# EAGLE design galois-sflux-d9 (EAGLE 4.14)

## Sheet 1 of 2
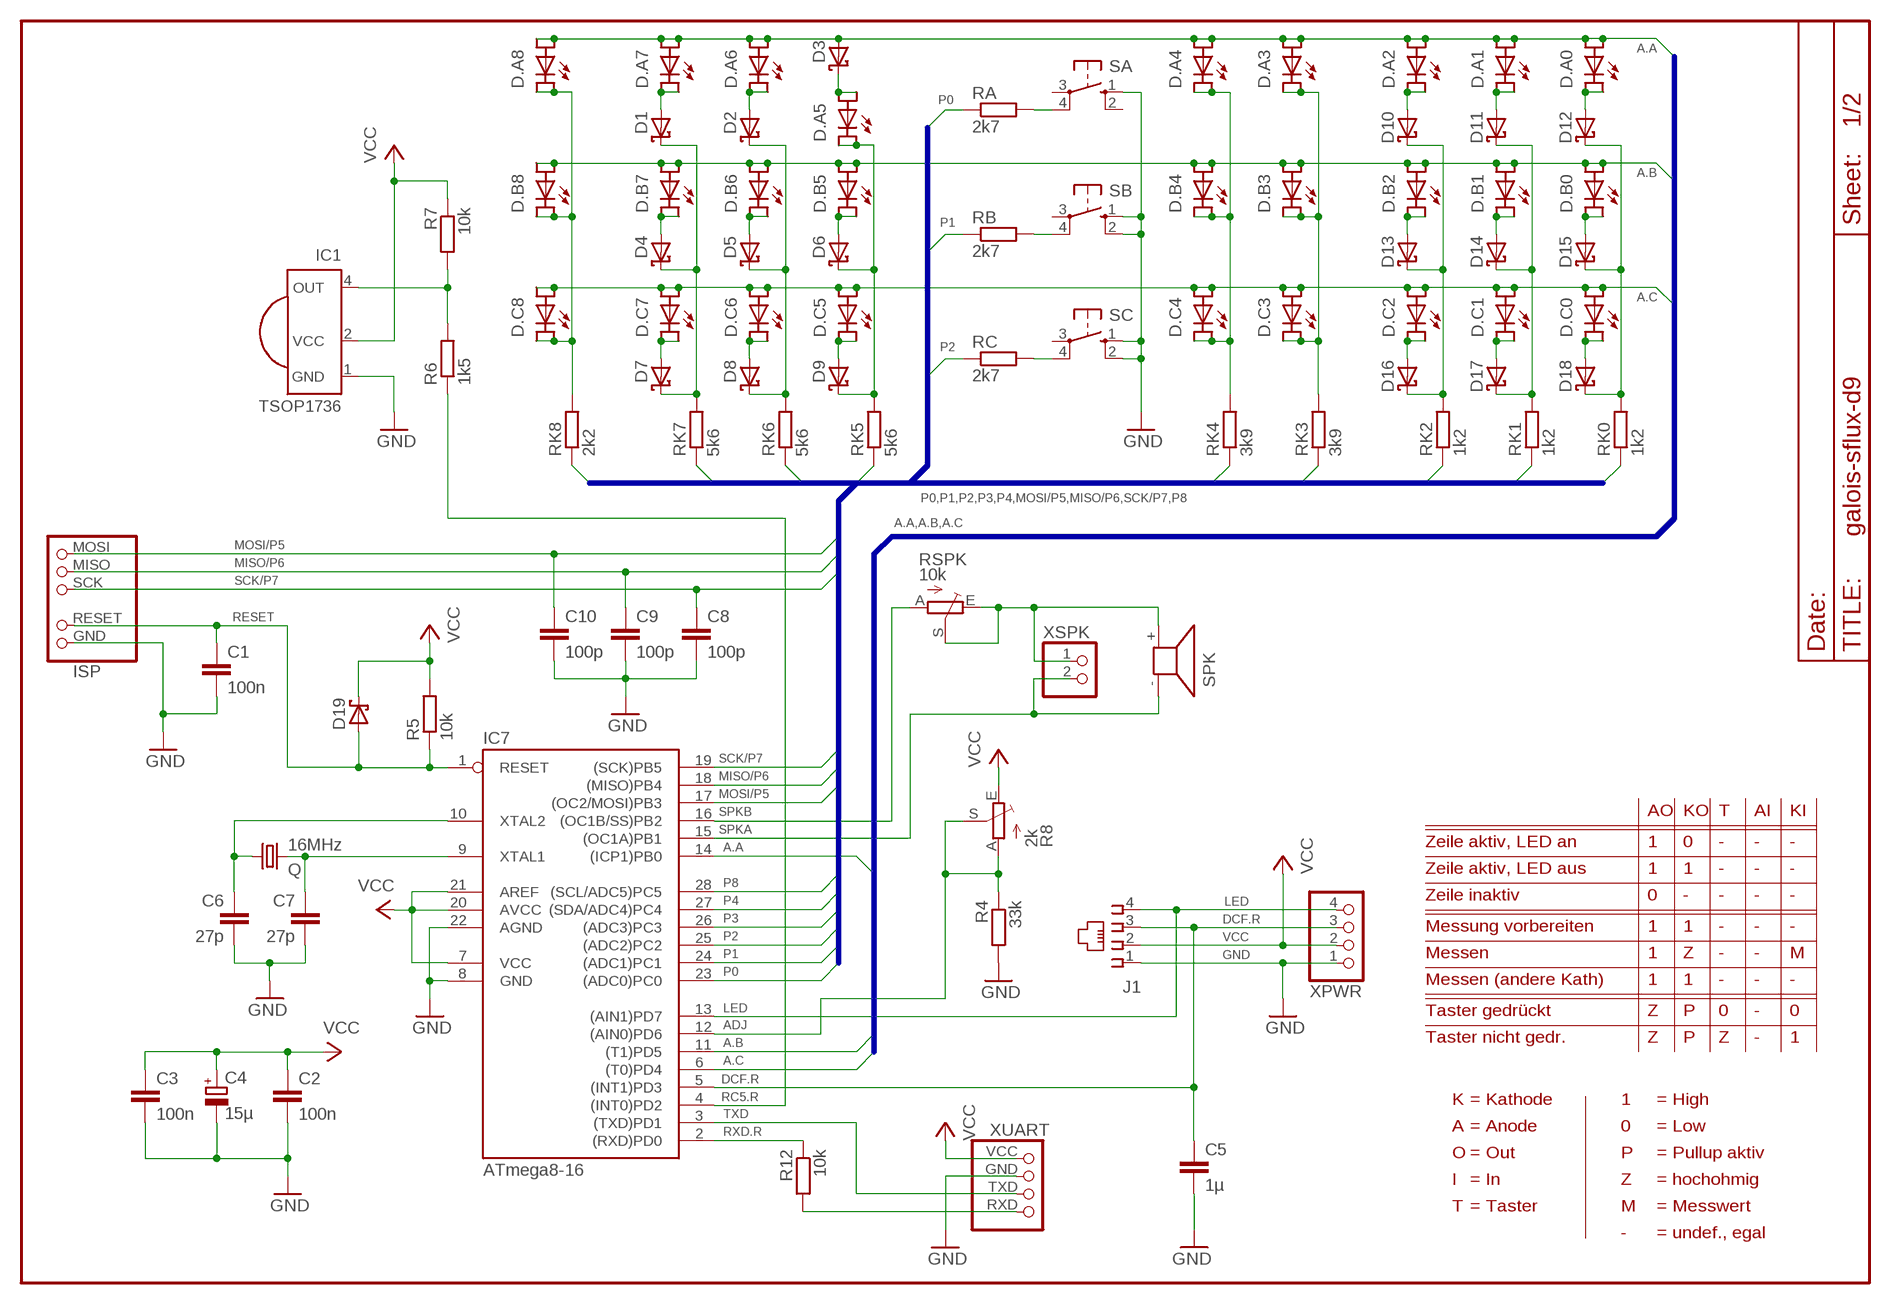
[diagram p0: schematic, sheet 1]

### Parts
C1  100n  C-EU050-024X044  [C050-024X044]
C2  100n  C-EU050-024X044  [C050-024X044]
C3  100n  C-EU050-024X044  [C050-024X044]
C4  15µ  CPOL-EUE1.8-4  [E1,8-4]
C5  1µ  C-EU050-024X044  [C050-024X044]
C6  27p  C-EU025-025X050  [C025-025X050]
C7  27p  C-EU025-025X050  [C025-025X050]
C8  100p  C-EU025-025X050  [C025-025X050]
C9  100p  C-EU025-025X050  [C025-025X050]
C10  100p  C-EU025-025X050  [C025-025X050]
D1  BAT42  [DO35-10@1]
D2  BAT42-7  [DO35-7B]
D3  BAT42-2.5  [DO35-2.5]
D4  BAT42  [DO35-10]
D5  BAT42-5  [DO35-5]
D6  BAT42-5  [DO35-5]
D7  BAT42-2.5  [DO35-2.5]
D8  BAT42-2.5  [DO35-2.5]
D9  BAT42-2.5  [DO35-2.5]
D10  BAT42  [DO35-10]
D11  BAT42  [DO35-10]
D12  BAT42  [DO35-10]
D13  BAT42  [DO35-10]
D14  BAT42  [DO35-10]
D15  BAT42  [DO35-10]
D16  BAT42  [DO35-10@1]
D17  BAT42-5  [DO35-5]
D18  BAT42  [DO35-10@1]
D19  BAT42  [DO35-10@1]
D.A0  LEDFLUX  [SFLUX]
D.A1  LEDFLUX  [SFLUX]
D.A2  LEDFLUX  [SFLUX]
D.A3  LEDFLUX  [SFLUX]
D.A4  LEDFLUX  [SFLUX]
D.A5  LEDFLUX  [SFLUX]
D.A6  LEDFLUX  [SFLUX]
D.A7  LEDFLUX  [SFLUX]
D.A8  LEDFLUX  [SFLUX]
D.B0  LEDFLUX  [SFLUX]
D.B1  LEDFLUX  [SFLUX]
D.B2  LEDFLUX  [SFLUX]
D.B3  LEDFLUX  [SFLUX]
D.B4  LEDFLUX  [SFLUX]
D.B5  LEDFLUX  [SFLUX]
D.B6  LEDFLUX  [SFLUX]
D.B7  LEDFLUX  [SFLUX]
D.B8  LEDFLUX  [SFLUX]
D.C0  LEDFLUX  [SFLUX]
D.C1  LEDFLUX  [SFLUX]
D.C2  LEDFLUX  [SFLUX]
D.C3  LEDFLUX  [SFLUX]
D.C4  LEDFLUX  [SFLUX]
D.C5  LEDFLUX  [SFLUX]
D.C6  LEDFLUX  [SFLUX]
D.C7  LEDFLUX  [SFLUX]
D.C8  LEDFLUX  [SFLUX]
IC1  TSOP1736  TSOPH  [TSOP-H]
IC7  ATmega8-16  MEGA8  [DIL28-3]
ISP  ISP  [PINHD6.ISP]
J1  MODULAR4  [MODULAR4-1]
Q  16MHz  CRYTALHC18U-V  [HC18U-V]
R4  33k  R-EU_0204/5  [0204/5]
R5  10k  R-EU_0204/5  [0204/5]
R6  1k5  R-EU_0204/5  [0204/5]
R7  10k  R-EU_0204/7  [0204/7]
R8  2k  TRIM_EU-S75H  [S75H]
R12  10k  R-EU_0204/5  [0204/5]
RA  2k7  R-EU_0204/7  [0204/7]
RB  2k7  R-EU_0204/5  [0204/5]
RC  2k7  R-EU_0204/5  [0204/5]
RK0  1k2  R-EU_0204/5  [0204/5]
RK1  1k2  R-EU_0204/5  [0204/5]
RK2  1k2  R-EU_0204/5  [0204/5]
RK3  3k9  R-EU_0204/5  [0204/5]
RK4  3k9  R-EU_0204/5  [0204/5]
RK5  5k6  R-EU_0204/5  [0204/5]
RK6  5k6  R-EU_0204/5  [0204/5]
RK7  5k6  R-EU_0204/5  [0204/5]
RK8  2k2  R-EU_0204/5  [0204/5]
RSPK  10k  TRIM_EU-S75H  [S75H]
SA  10-XX  [B3F-10XX]
SB  10-XX  [B3F-10XX]
SC  10-XX  [B3F-10XX]
SPK  AL11P  [AL11P]
XPWR  PINHD-1X4  [1X04]
XSPK  PINHD-1X2  [1X02]
XUART  UART  [PINHD4.UART]

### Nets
A.A: D3.A D.A0.A1 D.A0.A2 D.A1.A1 D.A1.A2 D.A2.A1 D.A2.A2 D.A3.A1 D.A3.A2 D.A4.A1 D.A4.A2 D.A6.A1 D.A6.A2 D.A7.A1 D.A7.A2 D.A8.A1 D.A8.A2 IC7.14((ICP1)PB0)
A.B: D.B0.A1 D.B0.A2 D.B1.A1 D.B1.A2 D.B2.A1 D.B2.A2 D.B3.A1 D.B3.A2 D.B4.A1 D.B4.A2 D.B5.A1 D.B5.A2 D.B6.A1 D.B6.A2 D.B7.A1 D.B7.A2 D.B8.A1 D.B8.A2 IC7.11((T1)PD5)
A.C: D.C0.A1 D.C0.A2 D.C1.A1 D.C1.A2 D.C2.A1 D.C2.A2 D.C3.A1 D.C3.A2 D.C4.A1 D.C4.A2 D.C5.A1 D.C5.A2 D.C6.A1 D.C6.A2 D.C7.A1 D.C7.A2 D.C8.A1 D.C8.A2 IC7.6((T0)PD4)
ADJ: IC7.12((AIN0)PD6) R4.1 R8.A R8.S
D.A3: D.A3.K1 D.A3.K2 D.B3.K1 D.B3.K2 D.C3.K1 D.C3.K2 RK3.2
DCF.R: C5.1 IC7.5((INT1)PD3) J1.3 XPWR.3 ; also sheet 2
GND: C1.2 C2.2 C3.2 C4.- C5.2 C6.2 C7.2 C8.2 C9.2 C10.2 IC1.1(GND) IC7.8(GND) IC7.22(AGND) ISP.GND J1.1 R4.2 SA.1(S) SB.1(S) SB.2(S1) SC.1(S) SC.2(S1) XPWR.1 XUART.GND ; also sheet 2
K0: D12.C D15.C D18.C RK0.2
K1: D11.C D14.C D17.C RK1.2
K2: D10.C D13.C D16.C RK2.2
K4: D.A4.K1 D.A4.K2 D.B4.K1 D.B4.K2 D.C4.K1 D.C4.K2 RK4.2
K5: D6.C D9.C D.A5.K1 D.A5.K2 RK5.2
K6: D2.C D5.C D8.C RK6.2
K7: D1.C D4.C D7.C RK7.2
K8: D.A8.K1 D.A8.K2 D.B8.K1 D.B8.K2 D.C8.K1 D.C8.K2 RK8.2
LED: IC7.13((AIN1)PD7) J1.4 XPWR.4 ; also sheet 2
MISO/P6: C9.1 IC7.18((MISO)PB4) ISP.MISO RK6.1
MOSI/P5: C10.1 IC7.17((OC2/MOSI)PB3) ISP.MOSI RK5.1
N$1: D7.A D.C7.K1 D.C7.K2
N$2: D8.A D.C6.K1 D.C6.K2
N$3: D9.A D.C5.K1 D.C5.K2
N$4: D18.A D.C0.K1 D.C0.K2
N$5: D13.A D.B2.K1 D.B2.K2
N$6: D14.A D.B1.K1 D.B1.K2
N$7: D17.A D.C1.K1 D.C1.K2
N$8: D16.A D.C2.K1 D.C2.K2
N$9: D15.A D.B0.K1 D.B0.K2
N$10: D12.A D.A0.K1 D.A0.K2
N$11: D11.A D.A1.K1 D.A1.K2
N$12: D10.A D.A2.K1 D.A2.K2
N$13: D1.A D.A7.K1 D.A7.K2
N$14: D4.A D.B7.K1 D.B7.K2
N$15: D5.A D.B6.K1 D.B6.K2
N$16: D2.A D.A6.K1 D.A6.K2
N$17: D3.C D.A5.A1 D.A5.A2
N$18: D6.A D.B5.K1 D.B5.K2
P0: IC7.23((ADC0)PC0) RA.1 RK0.1
P1: IC7.24((ADC1)PC1) RB.1 RK1.1
P2: IC7.25((ADC2)PC2) RC.1 RK2.1
P3: IC7.26((ADC3)PC3) RK3.1
P4: IC7.27((SDA/ADC4)PC4) RK4.1
P8: IC7.28((SCL/ADC5)PC5) RK8.1
RC5: IC1.4(OUT) R6.2 R7.2
RC5.R: IC7.4((INT0)PD2) R6.1
RESET: C1.1 D19.A IC7.1(RESET) ISP.RESET R5.1
RXD: R12.2 XUART.RXD
RXD.R: IC7.2((RXD)PD0) R12.1
SA.R: RA.2 SA.4(P1)
SB.R: RB.2 SB.4(P1)
SC.R: RC.2 SC.4(P1)
SCK/P7: C8.1 IC7.19((SCK)PB5) ISP.SCK RK7.1
SPK.R: RSPK.E RSPK.S SPK.+ XSPK.1
SPKA: IC7.15((OC1A)PB1) SPK.- XSPK.2
SPKB: IC7.16((OC1B/SS)PB2) RSPK.A
TXD: IC7.3((TXD)PD1) XUART.TXD
VCC: C2.1 C3.1 C4.+ D19.C IC1.2(VCC) IC7.7(VCC) IC7.20(AVCC) IC7.21(AREF) J1.2 R5.2 R7.1 R8.E XPWR.2 XUART.VCC ; also sheet 2
XTAL1: C6.1 IC7.10(XTAL2) Q.1
XTAL2: C7.1 IC7.9(XTAL1) Q.2
Unconnected: SA.2(S1) SA.3(P) SB.3(P) SC.3(P)

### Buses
P0,P1,P2,P3,P4,MOSI/P5,MISO/P6,SCK/P7,P8
A.A,A.B,A.C

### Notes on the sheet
- AO | KO | T | AI | KI
- Zeile aktiv, LED an | 1 | 0 | - | - | -
- Zeile aktiv, LED aus | 1 | 1 | - | - | -
- Zeile inaktiv | 0 | - | - | - | -
- Messung vorbereiten | 1 | 1 | - | - | -
- Messen | 1 | Z | - | - | M
- Messen (andere Kath) | 1 | 1 | - | - | -
- Taster gedrückt | Z | P | 0 | - | 0
- Taster nicht gedr. | Z | P | Z | - | 1
- K | = Kathode | 1 | = High
- A | = Anode | 0 | = Low
- O | = Out | P | = Pullup aktiv
- I | = In | Z | = hochohmig
- T | = Taster | M | = Messwert
- - | = undef., egal

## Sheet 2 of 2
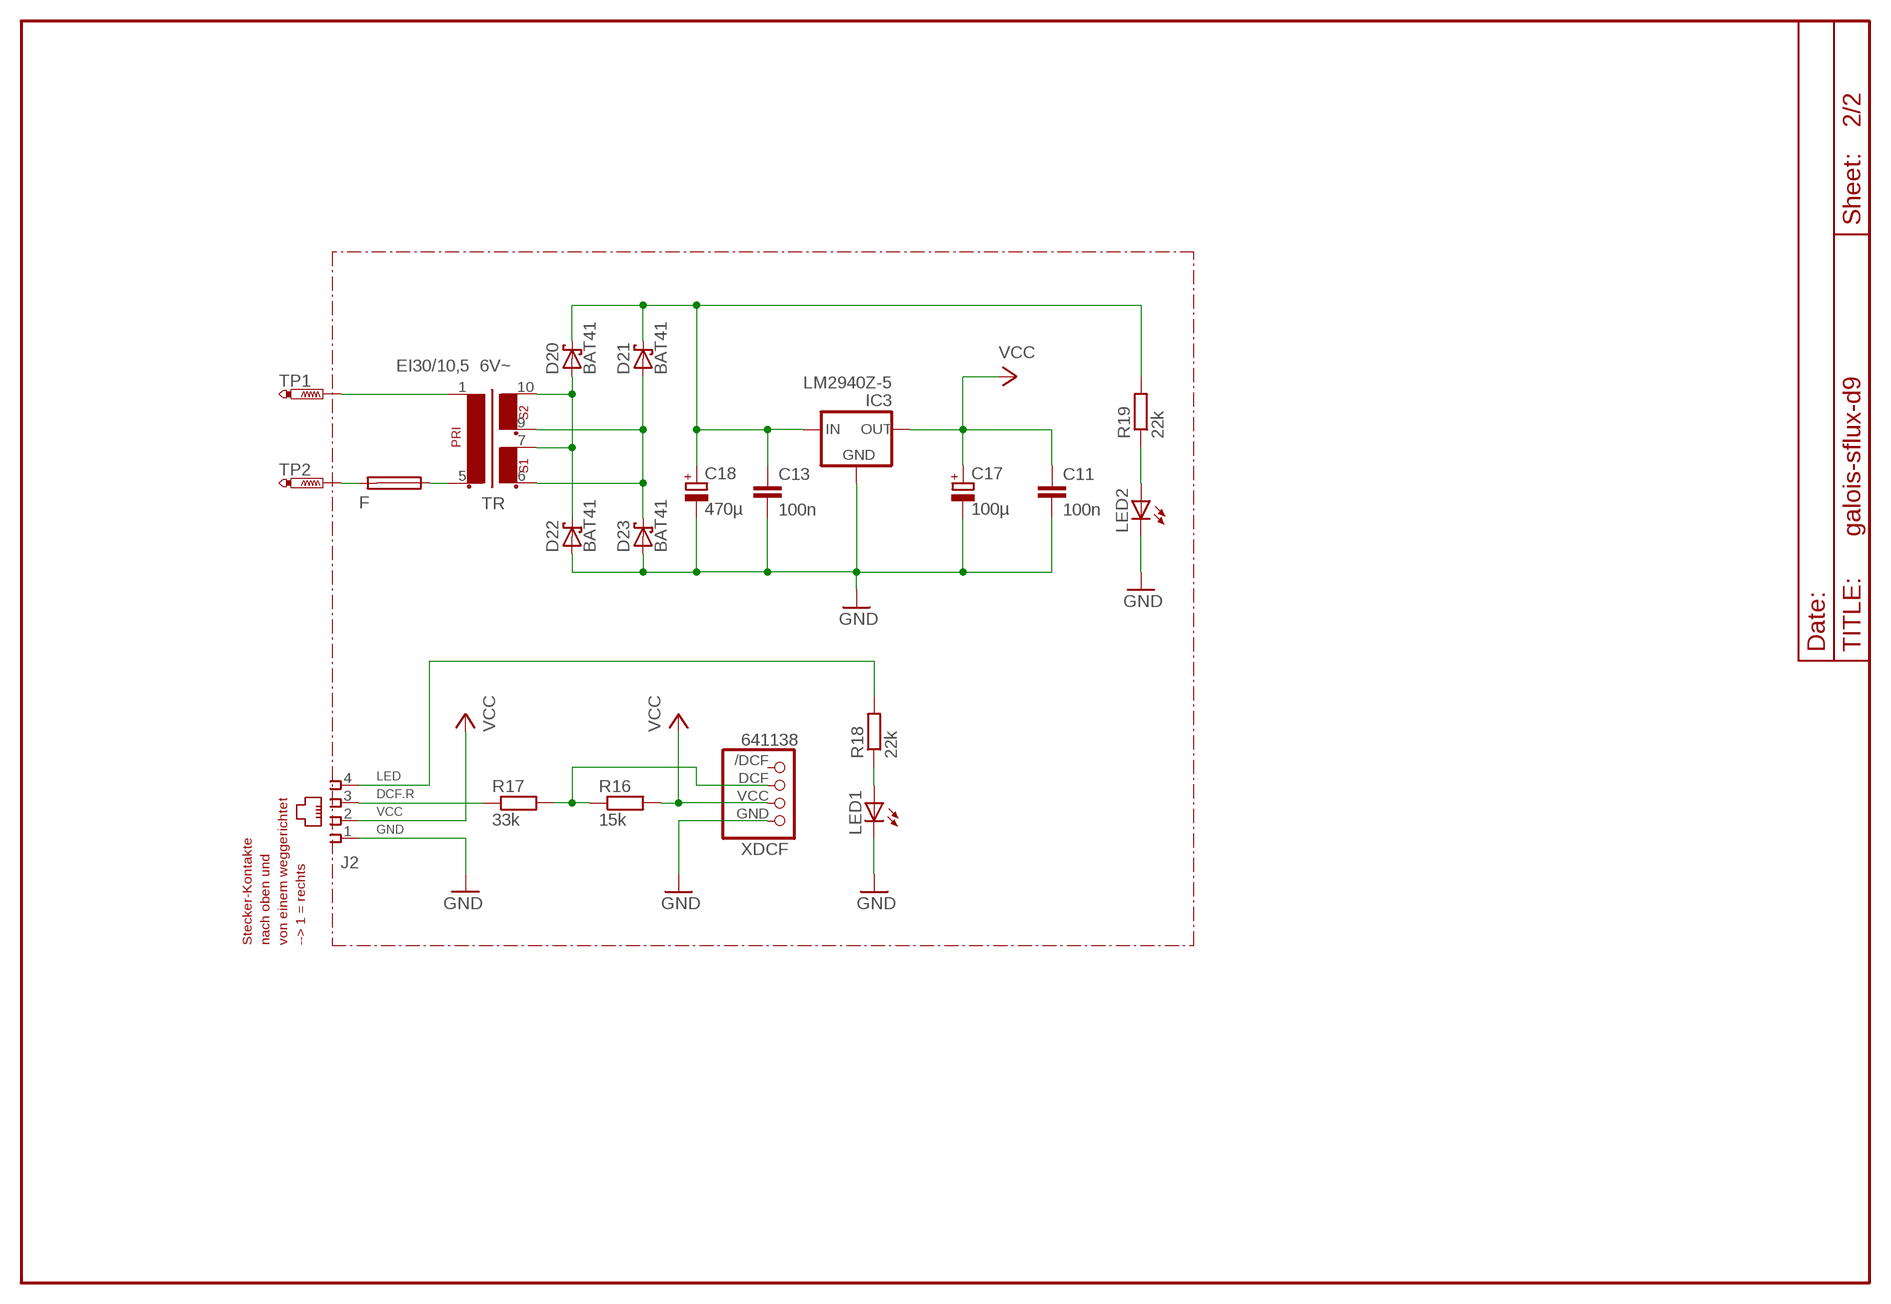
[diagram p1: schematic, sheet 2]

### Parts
C11  100n  C-EU050-024X044  [C050-024X044]
C13  100n  C-EU050-024X044  [C050-024X044]
C17  100µ  CPOL-EUE2.5-6  [E2,5-6]
C18  470µ  CPOL-EUE5-10.5  [E5-10,5]
D20  BAT41  BAT42  [DO35-10]
D21  BAT41  BAT42  [DO35-10]
D22  BAT41  BAT42  [DO35-10]
D23  BAT41  BAT42  [DO35-10]
F  F457  [F457]
IC3  LM2940Z-5  78XXS  [78XXS]
J2  MODULAR4H  [MODULAR4-1H]
LED1  LED3MM  [LED3MM]
LED2  LED3MM  [LED3MM]
R16  15k  R-EU_0207/10  [0207/10]
R17  33k  R-EU_0207/10  [0207/10]
R18  22k  R-EU_0207/10  [0207/10]
R19  22k  R-EU_0204/7  [0204/7]
TP1  PTR1PAD1-20Y  [P1-20Y]
TP2  PTR1PAD1-20Y  [P1-20Y]
TR  EI30/10,5 6V~  EI30-2  [EI30-2]
XDCF  641138  DCFV  [PINHEAD7-4.DCF]

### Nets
6V.A: D21.A D23.C TR.6 TR.9
6V.B: D20.A D22.C TR.7 TR.10
230V.A: TP1.1(TP) TR.1
230V.B: F.1 TR.5
DCF: R16.1 R17.2 XDCF.DCF
DCF.R: J2.3 R17.1 ; also sheet 1
GND: C11.2 C13.2 C17.- C18.- D22.A D23.A IC3.GND J2.1 LED1.K(C) LED2.K(C) XDCF.GND ; also sheet 1
LED: J2.4 R18.2 ; also sheet 1
LED1: LED1.A R18.1
LED2: LED2.A R19.1
N$19: F.2 TP2.1(TP)
V_IN: C13.1 C18.+ D20.C D21.C IC3.IN R19.2
VCC: C11.1 C17.+ IC3.OUT J2.2 R16.2 XDCF.VCC ; also sheet 1
Unconnected: XDCF./DCF

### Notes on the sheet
- Stecker-Kontakte | nach oben und | von einem weggerichtet | --> 1 = rechts

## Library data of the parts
C1-C3 C5-C11 C13 = rcl:C-EU: CAPACITOR, European symbol
C4 C17 C18 = rcl:CPOL-EU: POLARIZED CAPACITOR, European symbol
D1 D16 D18 D19 = diode:BAT42: DIODE
D2-D15 D17 D20-D23 = diode:BAT42*: DIODE
D.A0 D.A1-D.A8 D.B0 D.B1-D.B8 D.C0 D.C1-D.C8 = eigene:LEDFLUX
F = fuse:F457: FUSE HOLDER
IC1 = eigene:TSOP
IC3 = v-reg:78XXS: VOLTAGE REGULATOR
IC7 = atmel-gjl:MEGA8*
ISP = eigene:ISP
J1 J2 = eigene:MODULAR4*
LED1 LED2 = led:LED: LED
Q = crystal:CRYTAL: CRYSTAL
R4-R7 R12 R16-R19 RA RB RC RK0 RK1-RK8 = rcl:R-EU_: RESISTOR, European symbol
R8 RSPK = pot:TRIM_EU-: POTENTIOMETER
SA SB SC = switch-omron:10-XX: OMRON SWITCH
SPK = buzzer:AL11P: SPEAKER
TP1 TP2 = testpad:PTR1: TEST PIN
TR = trafo:EI30-2: TRANSFORMER 1 primary winding, 2 secondary windings ERA
XDCF = eigene:DCF*
XPWR = pinhead:PINHD-1X4: PIN HEADER
XSPK = pinhead:PINHD-1X2: PIN HEADER
XUART = eigene:UART

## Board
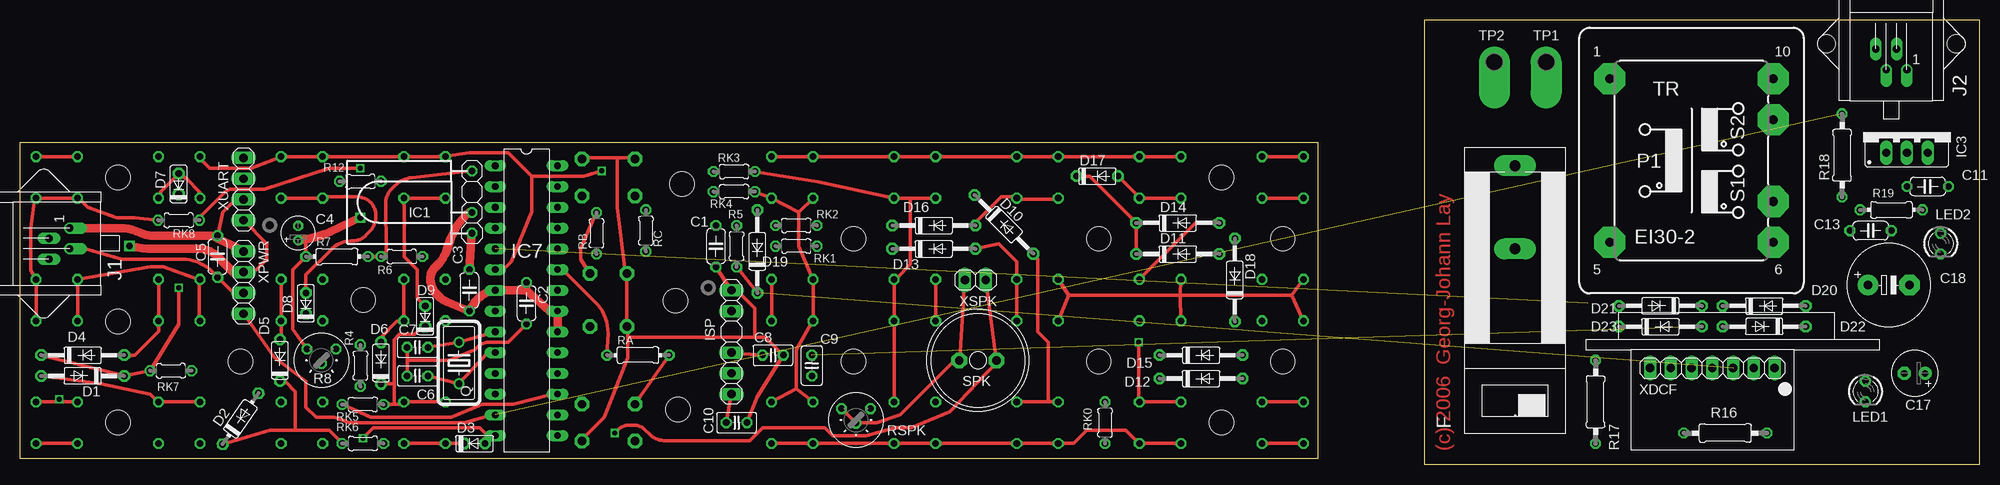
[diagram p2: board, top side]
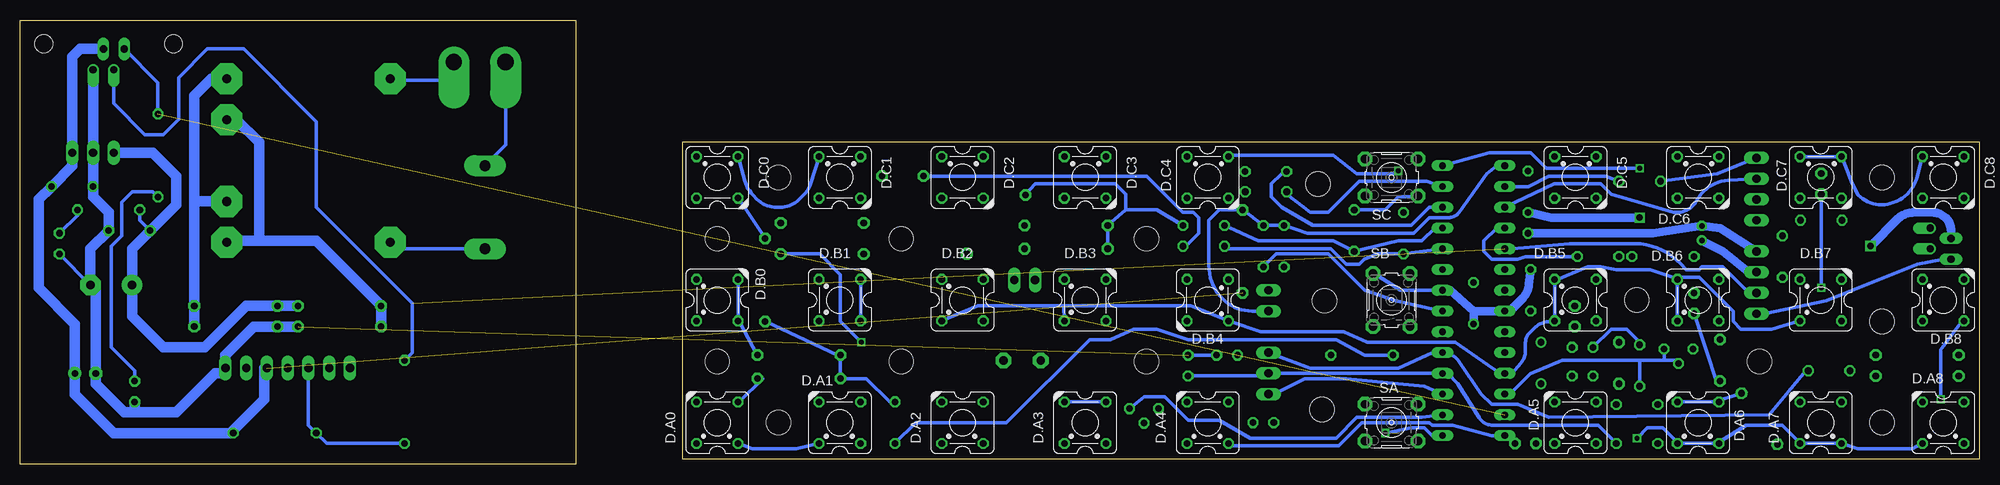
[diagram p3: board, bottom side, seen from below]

Size 239.71 x 54.29 mm. Coordinates in mm from the lower left corner, seen from the top.
Outline: 0,39.37 158.75,39.37 158.75,0.63 0,0.63 0,39.37
Outline: 171.77,0 239.71,0 239.71,54.29 171.77,54.29 171.77,0
Copper layers (1*16): Top 0.035mm / dielectric 1.5mm / Bottom 0.035mm
Design rules "default": minimum track width 10mil, minimum drill 0.6mm, track to track 8mil, track to pad 8mil, pad to pad 8mil, via to via 8mil, smd to smd 8mil, copper to edge 40mil, drill to drill 8mil, minimum pad ring 10mil, minimum via ring 8mil, stop-mask expansion 4mil, vias tented up to drill 0mil, thermal gap 10mil

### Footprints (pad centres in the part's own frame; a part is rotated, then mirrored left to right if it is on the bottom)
C050-024X044 = drill 0.813 octagon: 1 -2.54,0; 2 2.54,0
E1,8-4 = drill 0.711 pad 1.168 round: + -0.889,0 | drill 0.711 pad 1.168 octagon: - 0.889,0
C025-025X050 = drill 0.813 octagon: 1 -1.27,0; 2 1.27,0
E2,5-6 = drill 0.813 pad 1.6 round: + -1.27,0 | drill 0.813 pad 1.6 octagon: - 1.27,0
E5-10,5 = drill 1.016 pad 2.54 round: + -2.54,0 | drill 1.016 pad 2.54 octagon: - 2.54,0
DO35-10@1 = drill 0.813 pad 1.422 octagon: A 5.08,0; C -5.08,0
DO35-7B = drill 0.813 pad 1.422 octagon: A 3.81,0; C -3.81,0
DO35-2.5 = drill 0.813 pad 1.422 octagon: A 1.27,0; C -1.27,0
DO35-10 = drill 0.813 pad 1.422 octagon: A 5.08,0; C -5.08,0
DO35-5 = drill 0.813 pad 1.422 octagon: A 2.54,0; C -2.54,0
SFLUX = drill 0.8 octagon: A1 -2.54,2.54; A2 -2.54,-2.54; K1 2.54,2.54; K2 2.54,-2.54
F457 = drill 1.321 pad 2.54 long: 1 -5.08,0; 2 5.08,0
BOHRUNG_3MM = hole 3: 0,0
TSOP-H = drill 0.813 octagon: 1 -3.81,-5.08; 2 -1.27,-5.08; 4 3.81,-5.08
78XXS = drill 1.016 long: GND 0,-2.54; IN -2.54,-2.54; OUT 2.54,-2.54
DIL28-3 = drill 0.813 long: 1 -16.51,-3.81; 2 -13.97,-3.81; 3 -11.43,-3.81; 4 -8.89,-3.81; 5 -6.35,-3.81; 6 -3.81,-3.81; 7 -1.27,-3.81; 8 1.27,-3.81; 9 3.81,-3.81; 10 6.35,-3.81; 11 8.89,-3.81; 12 11.43,-3.81; 13 13.97,-3.81; 14 16.51,-3.81; 15 16.51,3.81; 16 13.97,3.81; 17 11.43,3.81; 18 8.89,3.81; 19 6.35,3.81; 20 3.81,3.81; 21 1.27,3.81; 22 -1.27,3.81; 23 -3.81,3.81; 24 -6.35,3.81; 25 -8.89,3.81; 26 -11.43,3.81; 27 -13.97,3.81; 28 -16.51,3.81
PINHD6.ISP = drill 1.016 long: GND -6.35,0; MISO 3.81,0; MOSI 6.35,0; RESET -3.81,0; SCK 1.27,0
MODULAR4-1 = drill 0.889 offset: 1 1.905,-1.27; 3 -0.635,-1.27 | drill 0.889 long: 2 0.635,1.27; 4 -1.905,1.27
MODULAR4-1H = drill 0.889 offset: 1 1.905,-1.27; 3 -0.635,-1.27 | drill 0.889 long: 2 0.635,1.27; 4 -1.905,1.27 | hole 2.2: 7.938,1.905; -7.938,1.905
LED3MM = drill 0.813 octagon: A -1.27,0; K 1.27,0
HC18U-V = drill 0.813 round: 1 -2.54,0; 2 2.54,0
0204/5 = drill 0.813 octagon: 1 -2.54,0; 2 2.54,0
0204/7 = drill 0.813 octagon: 1 -3.81,0; 2 3.81,0
S75H = drill 0.813 octagon: A -1.778,-1.397; E 1.778,-1.397; S 0,0.381
0207/10 = drill 0.813 octagon: 1 -5.08,0; 2 5.08,0
B3F-10XX = drill 1.016 pad 1.778 octagon: 1 -3.251,2.261; 2 3.251,2.261; 3 -3.251,-2.261; 4 3.251,-2.261
AL11P = drill 1.016 pad 1.905 octagon: + 2.286,0; - -2.286,0
P1-20Y = drill 2.007 pad 3.81 offset: 1 0,0
EI30-2 = drill 1.118 pad 3.81 octagon: 1 -10.008,10.008; 5 -10.008,-10.008; 6 10.008,-10.008; 7 10.008,-5.004; 9 10.008,5.004; 10 10.008,10.008
PINHEAD7-4.DCF = drill 1.016 long: 2 -5.08,0; 4 0,0; 6 5.08,0; /DCF -7.62,0; DCF -2.54,0; GND 7.62,0; VCC 2.54,0
1X04 = drill 1.016 long: 1 -3.81,0; 2 -1.27,0; 3 1.27,0; 4 3.81,0
1X02 = drill 1.016 long: 1 -1.27,0; 2 1.27,0
PINHD4.UART = drill 1.016 long: GND -1.27,0; RXD 3.81,0; TXD 1.27,0; VCC -3.81,0

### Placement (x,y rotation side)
C1  85.09,26.67 270 top
C2  61.91,19.69 270 top
C3  54.93,21.27 90 top
C4  33.97,28.26 90 top
C5  24.13,25.4 90 top
C6  48.58,10.79 180 top
C7  48.58,14.29 180 top
C8  92.07,13.34 0 top
C9  96.84,12.07 90 top
C10  87.63,5.08 0 top
C11  233.36,33.97 180 top
C13  226.38,28.58 0 top
C17  231.78,11.11 180 top
C18  228.6,21.91 0 top
D1  7.62,10.79 180 top
D2  26.93,5.56 55 top
D3  55.56,2.54 0 top
D4  7.62,13.34 0 top
D5  31.75,12.7 90 top
D6  44.13,12.38 90 top
D7  19.37,34.29 90 top
D8  34.92,19.69 90 top
D9  49.53,18.1 90 top
D10  120.33,29.34 315 top
D11  141.6,25.72 0 top
D12  144.46,10.48 0 top
D13  111.76,26.35 0 top
D14  141.6,29.53 0 top
D15  144.46,13.34 0 top
D16  111.76,29.21 0 top
D17  131.76,35.24 0 top
D18  148.59,22.54 90 top
D19  90.17,26.03 90 top
D20  213.36,19.37 0 top
D21  200.66,19.37 180 top
D22  213.36,16.83 180 top
D23  200.66,16.83 0 top
D.A0  154.44,5.08 90 bottom
D.A1  139.44,5.08 90 bottom
D.A2  124.44,5.08 90 bottom
D.A3  109.44,5.08 90 bottom
D.A4  94.44,5.08 90 bottom
D.A5  49.45,5.08 90 bottom
D.A6  34.45,5.08 90 bottom
D.A7  19.45,5.08 90 bottom
D.A8  4.45,5.08 90 bottom
D.B0  154.44,20.08 0 bottom
D.B1  139.44,20.08 0 bottom
D.B2  124.44,20.08 0 bottom
D.B3  109.44,20.08 0 bottom
D.B4  94.44,20.08 180 bottom
D.B5  49.45,20.08 0 bottom
D.B6  34.45,20.08 0 bottom
D.B7  19.45,20.08 0 bottom
D.B8  4.45,20.08 0 bottom
D.C0  154.44,35.08 270 bottom
D.C1  139.44,35.08 270 bottom
D.C2  124.44,35.08 270 bottom
D.C3  109.44,35.08 270 bottom
D.C4  94.44,35.08 270 bottom
D.C5  49.45,35.08 270 bottom
D.C6  34.45,35.08 270 bottom
D.C7  19.45,35.08 270 bottom
D.C8  4.45,35.08 270 bottom
F  182.88,31.43 90 top
H$3  [BOHRUNG_3MM]  80.96,34.29 0 top
H$6  [BOHRUNG_3MM]  80.15,20 0 top
H$7  [BOHRUNG_3MM]  80.47,6.67 0 top
H$A1  [BOHRUNG_3MM]  146.94,5.08 0 top
H$A2  [BOHRUNG_3MM]  11.95,5.08 0 top
H$A3  [BOHRUNG_3MM]  26.95,12.58 0 top
H$A4  [BOHRUNG_3MM]  101.94,12.58 0 top
H$A5  [BOHRUNG_3MM]  154.44,12.58 0 top
H$A6  [BOHRUNG_3MM]  11.95,17.46 0 top
H$A7  [BOHRUNG_3MM]  131.94,12.58 0 top
H$B1  [BOHRUNG_3MM]  146.94,35.08 0 top
H$B2  [BOHRUNG_3MM]  11.95,35.08 0 top
H$B3  [BOHRUNG_3MM]  41.95,20.08 0 top
H$B4  [BOHRUNG_3MM]  101.94,27.58 0 top
H$B5  [BOHRUNG_3MM]  154.44,27.58 0 top
H$B7  [BOHRUNG_3MM]  131.94,27.58 0 top
IC1  50.16,32.07 90 top
IC3  230.82,40.64 0 top
IC7  61.91,20 270 top
ISP  87,14.92 270 top
J1  4.76,26.99 90 top
J2  228.92,49.53 0 top
LED1  225.74,8.89 270 top
LED2  234.95,26.99 270 top
Q  53.66,12.38 90 top
R4  41.59,12.07 90 top
R5  87.63,26.67 270 top
R6  46.67,25.4 180 top
R7  38.73,25.4 0 top
R8  36.83,12.7 180 top
R12  41.59,34.61 180 top
R16  208.6,3.81 0 top
R17  192.72,7.62 270 top
R18  222.88,37.78 90 top
R19  228.92,31.12 180 top
RA  75.56,13.34 0 top
RB  70.49,28.26 90 top
RC  76.52,28.58 90 top
RK0  132.72,5.08 90 top
RK1  94.93,26.67 0 top
RK2  94.93,29.21 0 top
RK3  87.32,35.8 0 top
RK4  87.31,33.34 0 top
RK5  41.91,7.3 0 top
RK6  41.91,2.54 180 top
RK7  18.41,11.43 180 top
RK8  19.37,29.84 180 top
RSPK  102.24,5.4 180 top
SA  71.94,5.08 180 bottom
SB  71.94,20.08 90 bottom
SC  71.94,35.08 0 bottom
SPK  117.16,12.7 180 top
TP1  186.69,49.21 180 top
TP2  180.34,49.21 180 top
TR  204.47,37.15 0 top
U$12  [BOHRUNG_3MM]  not placed on the board
XDCF  207.01,11.75 0 top
XPWR  27.3,22.23 270 top
XSPK  116.84,22.54 0 top
XUART  27.3,33.66 90 top

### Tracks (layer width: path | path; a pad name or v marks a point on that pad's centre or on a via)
6V.A
  Bottom 1.27: D23.C D21.A 203.52,27.3 210.5,27.3 | TR.9 213.28,42.15 210.5,39.37 210.5,27.3 | TR.6 214.31,27.3 210.5,27.3
6V.B
  Bottom 1.27: D22.C D20.A 218.44,32.07 | TR.10 216.37,47.16 218.44,45.09 218.44,32.07 | TR.7 218.36,32.14 218.44,32.07
230V.A
  Bottom 0.406: TP1.1 186.69,46.99 193.99,46.99 194.31,47.31 TR.1
230V.B
  Bottom 0.406: F.1 193.67,26.35 194.31,26.99 | TR.5 194.63,27.3 | 194.31,26.99 TR.5 | 194.31,26.99 TR.5
A.A  (via drill 0.6)
  Top 0.406: D.A1.A1 D.A1.A2 136.84,2.54 135.25,4.13 130.49,4.13 128.91,2.54 D.A2.A1 D.A2.A2 D.A3.A1 D.A3.A2 D.A4.A1 D.A4.A2 | D.A0.A2 D.A0.A1 | D.A8.A1 D.A8.A2 | 57.15,3.49 IC7.14 | v41.91,3.17 43.18,4.45 56.2,4.45 57.15,3.49 | D3.A 56.83,3.17 57.15,3.49
  Bottom 0.406: IC7.14 59.69,3.49 64.45,4.76 66.99,4.76 67.31,5.08 75.56,5.08 78.42,2.22 91.44,2.22 91.76,2.54 D.A4.A2 | D.A1.A1 144.78,1.91 150.18,1.91 D.A0.A2 | D.A8.A1 8.26,1.91 14.92,1.91 D.A7.A2 | 32.07,2.54 28.57,4.76 24.13,4.76 21.98,2.62 D.A7.A1 D.A7.A2 | 31.75,2.54 D.A6.A2 32.07,2.54 | 32.07,2.54 D.A6.A1 36.98,2.7 38.73,4.45 40.64,4.45 v41.91,3.17 | D.A7.A2 16.83,2.54
A.B
  Top 0.406: 128.27,20.64 141.92,20.64 | 141.92,20.64 155.57,20.64 | 141.92,20.64 D.B1.A1 | D.B2.A2 128.27,20.64 | 128.27,20.64 D.B2.A1 | D.B3.A2 D.B3.A1 | 141.92,20.64 D.B1.A2 | 155.57,20.64 D.B0.A1 | 155.57,20.64 D.B0.A2 | D.B4.A1 D.B4.A2 | D.B8.A2 D.B8.A1 7.06,22.62 15.88,24.13 17.46,24.13 21.91,22.54 | D.B7.A2 21.91,17.78 21.91,22.54 | 21.91,22.54 D.B7.A1
  Bottom 0.406: 112.08,19.37 122.56,19.37 D.B2.A2 | D.B7.A2 25.4,16.51 29.21,16.51 30.16,17.46 30.16,18.73 34.29,22.86 37.15,22.86 36.98,22.7 | 112.08,19.37 D.B3.A2 | 36.98,22.7 40.32,23.81 44.45,23.81 46.35,24.13 47.94,24.13 51.75,22.54 51.83,22.62 D.B5.A1 D.B5.A2 52.07,17.46 | 91.76,17.46 87.95,16.19 77.79,16.19 74.93,14.92 64.13,14.92 58.74,11.11 IC7.11 57.15,11.11 56.11,12.37 arc-41 55.56,13.86 55.56,14.89 arc45 55.09,16.03 54.57,16.55 arc45 52.5,17.46 52.07,17.46 | 91.76,17.46 91.84,17.54 D.B4.A1 | 112.08,19.37 96.52,19.37 91.76,17.46 | 52.07,17.46 D.B5.A2 | D.B6.A2 37.07,17.54 36.98,17.62 D.B6.A1 36.98,22.7
A.C  (via drill 0.6)
  Top 0.406: IC7.6 59.05,23.81 60.04,24.79 62.55,30.86 62.55,35.24 | 62.55,35.24 59.69,38.1 54.93,38.1 51.98,37.7 D.C5.A2 D.C5.A1 D.C6.A2 D.C6.A1 28.26,36.2 23.18,36.2 21.91,37.46 21.98,37.54 D.C7.A2 | D.C0.A1 D.C0.A2 | D.C1.A2 D.C1.A1 D.C2.A2 D.C2.A1 D.C3.A2 D.C3.A1 D.C4.A2 D.C4.A1 | D.C8.A1 D.C8.A2 | v71.12,35.88 68.9,35.24 62.55,35.24
  Bottom 0.406: D.C4.A1 91.91,37.63 91.76,37.78 79.06,37.78 76.2,35.56 71.75,35.56 v71.12,35.88 | D.C0.A1 151.91,37.6 151.1,34.71 arc-30 150.04,32.88 149.6,32.44 arc-45 147.17,31.43 146.73,31.43 arc-45 144.48,32.36 143.83,33.01 arc-27 143.01,34.37 D.C1.A2 | D.C8.A2 7.61,35.25 arc30 8.87,33.04 arc45 11.98,31.75 arc45 14.83,32.93 15.56,34.29 16.83,37.46 | 16.83,37.46 16.91,37.54 D.C7.A1 | D.C7.A2 16.98,37.62 16.83,37.46
ADJ
  Bottom 0.406: IC7.12 57.47,8.57 54.96,11.08 51.04,12.7 41.59,12.7 | 41.59,12.7 R4.1 | R8.S 36.83,12.7 38.73,12.7 | 38.73,12.7 41.59,12.7 | R8.A 38.61,12.83 38.73,12.7
D.A3
  Top 0.406: D.A3.K2 D.B3.K2 D.B3.K1 107.31,22.86 108.9,24.45 108.9,32.54 | RK3.2 97.55,34.53 D.C3.K1 | 108.9,32.54 D.C3.K1 | 108.9,32.54 D.C3.K2 | D.C3.K1 106.91,32.16 | D.C3.K1 106.91,32.61 107,32.7
  Bottom 0.406: D.A3.K2 D.A3.K1
DCF
  Bottom 0.406: R17.2 202.25,2.54 R16.1 204.47,4.76 XDCF.DCF
DCF.R  (1 unrouted)
  Top 0.406: XPWR.3 26.04,20.95 C5.1 23.22,23.77 arc45 19.29,25.08 12.38,25.08 7.94,26.35 J1.3
  Bottom 0.406: IC7.5 57.15,26.35 50.16,26.99 42.18,26.99 arc45 36.62,24.55 35.88,23.81 34.29,23.81 33.97,24.13 31.43,24.13 28.26,20.95 XPWR.3 | R17.1 191.77,13.65 191.77,19.69 203.52,31.43 203.52,41.91 212.41,50.8 216.85,50.8 220.34,47.31 220.34,42.23 222.25,40.32 224.47,40.32 228.28,44.13 J2.3
GND  (1 unrouted)
  Top 0.406: C10.2 90.17,8.25 C8.2 91.12,15.56 89.85,15.56 | 73.03,37.46 73.03,31.43 73.98,23.49 73.98,23.81 74.21,23.41 SB.2 SB.1 74.29,16.83 74.29,15.56 | SC.2 68.69,37.35 68.58,37.46 73.03,37.46 | SC.1 75.2,37.41 75.25,37.46 73.03,37.46 | C5.2 24.77,30.8 26.35,32.38 XUART.GND | C1.2 ISP.GND 87.63,21.27 89.85,19.05 89.85,15.56 | SA.1 68.62,2.82 68.58,2.86 71.44,5.71 74.29,13.02 74.29,15.56 | 74.29,15.56 89.85,15.56 | 47.31,12.7 C7.2 | 47.31,12.7 C6.2 | 47.31,12.7 52.45,12.7 55.59,14 55.86,14.27 arc-45 57.45,14.92 59.69,14.92 C2.2
  Top 1.016: IC1.1 C3.2 | 23.5,27.94 XPWR.1 | 23.5,27.94 C5.2 | J1.1 12.2,28.89 arc-24 14.66,28.3 arc24 16.28,27.94 23.5,27.94
  Bottom 0.406: C8.2 C9.2 | 54.99,23.37 55.12,23.05 | SB.2 74.13,23.33 70.8,21.27 IC7.22 | R4.2 41.59,14.92 43.18,16.51 45.09,16.51 C7.2 | C18.- LED2.K
  Bottom 1.016: IC1.1 40.01,28.26 C4.- 31.75,28.89 XPWR.1 | C3.2 54.99,23.37 54.94,23.82 55.13,22.02 arc39 56,20.2 57.47,18.73 IC7.8 61.91,18.73 | 61.91,18.73 C2.2 | IC7.22 64.77,21.27 61.91,18.73
  Bottom 1.27: D23.A D22.A 211.14,16.83 214.63,13.34 XDCF.GND 214.63,11.11 215.9,11.11 220.66,6.35 225.74,6.35 | J2.1 IC3.GND C11.2 230.82,32.7 228.92,30.8 C13.2 231.14,26.35 C18.- 230.5,21.27 C17.- 230.5,9.84 227.01,6.35 225.74,6.35 | 225.74,6.35 LED1.K
K0
  Bottom 0.406: D18.C 139.7,13.34 D15.C D12.C 136.21,10.48 133.35,7.62 RK0.2
K1
  Top 0.406: D17.C 130.81,35.24 D14.C D11.C
  Bottom 0.406: RK1.2 97.16,26.67 95.57,28.26 95.57,30.16 96.2,30.8 97.47,30.8 101.92,35.24 D17.C
K2
  Bottom 0.406: RK2.2 100.65,31.12 104.46,31.12 | 104.46,31.12 D16.C D13.C | D10.C 115.57,34.29 105.73,34.29 104.46,33.02 104.46,31.12
K4
  Top 0.406: RK4.2 D.C4.K1 95.25,30.8 | D.A4.K2 94.93,9.21 | 95.25,30.8 95.25,26.67 96.91,22.62 D.B4.K2 D.B4.K1 96.91,17.54 94.93,13.97 94.93,9.21 | D.C4.K2 95.25,30.8 | 97.16,7.62 D.A4.K1 94.93,9.21
K5
  Top 0.406: 46.99,7.62 D.A5.K2 46.91,7.54 | 46.91,7.54 46.99,7.62 | D9.C 49.21,16.83 48.26,15.88 46.35,15.88 45.72,15.24 45.72,9.84 | 45.72,9.84 D6.C | 45.72,7.3 45.72,9.84 | RK5.2 45.72,7.3 | 46.91,7.54 46.67,7.3 45.72,7.3 | 52.07,7.62 D.A5.K1 46.99,7.62
K6
  Top 0.406: RK6.2 37.78,4.13 33.66,4.13 | D2.C 30.48,4.13 33.66,4.13 | D5.C 32.39,10.16 33.66,8.89 33.66,4.13
  Bottom 0.406: D8.C 32.07,9.84 D5.C
K7  (via drill 0.6)
  Top 0.406: v19.37,21.59 19.37,17.14 RK7.2 D1.C D4.C
  Bottom 0.406: v19.37,21.59 D7.C
K8  (via drill 0.6)
  Top 0.406: D.A8.K1 D.A8.K2 4.45,7.62 v4.76,7.94 | RK8.2 13.97,30.16 11.77,30.16 8.26,31.43 7.15,32.54 D.C8.K2 D.C8.K1 1.74,32.54 1.27,28.89 1.27,23.81 1.83,22.62 D.B8.K1 D.B8.K2
  Bottom 0.406: v4.76,7.94 4.76,13.97 2.15,17.54 D.B8.K2
LED  (1 unrouted)
  Top 0.406: IC7.13 57.79,6.03 54.29,5.08 40.32,5.08 38.42,5.71 36.2,5.71 34.92,6.99 34.92,10.16 31.08,13.05 XPWR.4
  Bottom 0.406: J1.4 4.45,25.08 7.62,24.45 18.73,20 26.35,18.41 XPWR.4 | J2.4 222.88,46.67 R18.2
LED1
  Bottom 0.406: R18.1 223.52,33.34 226.06,33.34 227.33,32.07 227.33,27.94 228.6,26.67 228.6,14.29 225.74,11.43 LED1.A
LED2
  Bottom 0.406: R19.1 232.73,30.48 LED2.A
MISO/P6
  Bottom 0.406: RK6.1 46.67,4.76 59.57,4.76 arc58 61.21,5.67 63.82,9.84 65.09,11.11 IC7.18 ISP.MISO 87,10.79 C9.1
MOSI/P5
  Top 0.406: RK5.1 42.86,5.71 52.7,5.71 56.52,7.3 60.33,7.3 65.09,8.57 IC7.17 | ISP.MOSI C10.1
  Bottom 0.406: IC7.17 67.94,9.53 77.47,10.48 82.55,10.48 86.36,8.57 ISP.MOSI
N$1
  Top 0.406: D.C7.K1 16.91,32.62 16.83,32.7 17.14,33.02 17.14,33.34 D7.A 20.32,34.92 21.91,33.34 21.91,32.7 21.98,32.62 D.C7.K2
N$2
  Top 0.406: D.C6.K1 32.07,32.38 32.22,32.54 | D.C6.K1 D.C6.K2 36.83,32.7 41.22,32.7 arc-90 43.5,30.42 arc-45 42.64,28.35 42.34,28.05 arc-45 40.53,27.3 arc45 38.01,26.26 34.92,23.18 D8.A | D.C6.K1 31.75,32.38
N$3
  Top 0.406: D.C5.K2 D.C5.K1 46.91,32.3 46.99,31.12 46.99,25.4 48.58,23.81 48.58,20.32 D9.A
N$4
  Top 0.406: D.C0.K1 D.C0.K2
  Bottom 0.406: D18.A 151.76,32.38 151.91,32.52 D.C0.K1
N$5
  Top 0.406: D.B2.K2 D.B2.K1 121.91,24.78 119.7,26.99 D13.A
N$6
  Top 0.406: 136.91,22.6 136.84,22.54 | D.B1.K1 136.91,22.6 | D14.A 143.83,29.53 136.91,22.6
  Bottom 0.406: D.B1.K2 D.B1.K1
N$7
  Top 0.406: D.C1.K2 D.C1.K1 136.91,32.64 D17.A
N$8
  Top 0.406: 126.99,32.4 D.C2.K2 | 126.99,32.4 121.91,32.4 D.C2.K1 121.91,32.69 121.92,32.7 120.01,32.7 117.16,29.84 D16.A | 126.99,32.4 127,32.38
N$9
  Bottom 0.406: D.B0.K1 D.B0.K2 151.84,17.54 151.76,17.46 D15.A
N$10
  Top 0.406: D.A0.K2 D.A0.K1
  Bottom 0.406: D.A0.K2 151.76,7.62 148.91,10.48 D12.A
N$11  (via drill 0.6)
  Top 0.406: 136.84,13.65 136.84,7.62 D.A1.K2 D.A1.K1 | 136.84,13.65 136.84,14.29 | 136.84,13.65 v136.84,14.92
  Bottom 0.406: D11.A 141.92,25.72 139.38,23.18 139.38,17.46 v136.84,14.92
N$12
  Top 0.406: D.A2.K2 125.73,7.62 | 125.73,7.62 D.A2.K1 127,7.62 | 125.73,7.62 125.73,14.92 124.46,16.19 124.46,25.08 D10.A
N$13
  Top 0.406: D1.A 9.84,9.84 15.88,8.57 16.83,7.62 D.A7.K2 D.A7.K1
  Bottom 0.406: D.A7.K2 16.83,7.62
N$14
  Top 0.406: D.B7.K1 16.83,22.54 16.91,22.47 D.B7.K2 16.91,16.27 13.97,13.34 D4.A
  Bottom 0.406: D.B7.K1 16.83,22.54
N$15
  Top 0.406: 32.07,22.54 D.B6.K1 D.B6.K2 31.91,15.39 D5.A
N$16
  Bottom 0.406: D2.A 31.43,7.94 31.75,7.62 | 31.75,7.62 D.A6.K2 | 31.75,7.62 D.A6.K1
N$17
  Top 0.406: 52.07,2.54 D3.C | 52.07,2.54 D.A5.A1 | D.A5.A2 52.07,2.54
N$18
  Top 0.406: D.B5.K2 D.B5.K1 | D.B5.K2 46.75,17.54 | D6.A 44.13,15.56 46.04,17.46 46.99,17.46 D.B5.K2
N$19
  Bottom 0.406: TP2.1 180.34,39.05 F.2
P0
  Top 0.406: IC7.23 66.36,23.81 70.6,19.57 arc-41 71.89,16.02 RA.1
  Bottom 0.406: RA.1 75.25,13.34 78.74,15.24 96.84,15.24 100.65,16.51 103.5,16.51 106.36,15.24 108.9,15.24 119.06,5.08 130.18,5.08 RK0.1
P1
  Bottom 0.406: RK1.1 92.07,26.35 79.38,26.35 77.47,24.45 75.88,24.45 75.28,25.05 73.66,25.72 RB.1 IC7.24
P2
  Bottom 0.406: RK2.1 88.26,27.3 79.06,27.3 RC.1 71.12,27.3 68.26,27.3 66.67,28.89 IC7.25
P3
  Bottom 0.406: IC7.26 67.31,31.43 69.53,29.21 81.6,29.21 85.41,31.43 86.68,32.7 86.68,34.29 85.41,35.56 RK3.1
P4
  Bottom 0.406: IC7.27 67.63,34.61 75.88,34.61 79.69,30.8 81.91,30.8 84.77,33.02 RK4.1
P8  (via drill 0.6)
  Top 0.406: v41.59,36.2 37.78,36.2 29.84,33.66 25.94,33.66 arc45 25.02,33.27 21.91,30.16 RK8.1
  Bottom 0.406: IC7.28 60.01,38.1 54.93,38.1 53.02,36.2 v41.59,36.2
RC5
  Top 0.406: R7.2 R6.2 44.77,26.03 44.69,32.09 arc-40 45.43,33.68 45.8,34.05 arc-39 47.9,35.06 IC1.4
RC5.R
  Bottom 0.406: R6.1 55.56,25.4 56.52,25.08 59.69,25.08 60.64,26.03 60.64,27.3 59.05,28.89 IC7.4
RESET
  Bottom 0.406: IC7.1 59.05,36.51 60.33,35.56 63.65,30.85 arc55 64.97,30.16 67.31,30.16 69.22,28.26 82.23,28.26 C1.1 R5.1 D19.A 93.03,31.12 94.3,29.84 94.3,24.29 arc-45 92.61,20.22 arc-45 89.01,18.73 ISP.RESET
RXD
  Bottom 0.406: R12.2 32.07,35.56 XUART.RXD
RXD.R
  Bottom 0.406: R12.1 45.72,35.24 52.7,35.24 55.24,33.97 IC7.2
SA.R
  Top 0.406: SA.4 RA.2
SB.R
  Top 0.406: RB.2 68.58,26.35 68.58,25.08 69.53,23.49 SB.4
SC.R
  Bottom 0.406: RC.2 72.71,31.12 71.12,32.7 68.9,32.7 68.78,32.82 SC.4
SCK/P7
  Top 0.406: ISP.SCK C8.1
  Bottom 0.406: ISP.SCK 81.91,11.75 71.12,11.75 66.99,13.65 IC7.19 arc55 63.73,12.61 60.96,8.57 59.69,7.3 56.52,7.3 52.7,5.71 25.72,6.03 21.27,11.43 RK7.1
SPK.R
  Top 0.406: XSPK.1 114.94,12.7 SPK.+ 114.3,12.7 107.63,6.03 104.78,5.08 102.24,5.08 | 102.24,5.08 RSPK.S | RSPK.E 100.52,6.79 102.24,5.08
SPKA  (via drill 0.6)
  Top 0.406: 119.38,12.7 XSPK.2 | 119.38,12.7 SPK.- | 119.38,12.7 119.38,12.38 113.71,6.4 109,4.45 107,4.45 103.5,3.49 99.38,3.49 98.43,4.45 90.81,4.45 89.22,2.86 78.98,2.86 arc-45 76.94,3.7 76.47,4.17 arc45 75.05,4.76 74.49,4.76 arc45 73.07,4.17 v72.71,3.81
  Bottom 0.406: v72.71,3.81 69.53,4.45 67.94,4.45 66.99,3.49 IC7.15
SPKB
  Bottom 0.406: IC7.16 68.26,5.71 76.2,5.71 78.74,3.17 89.22,3.17 93.03,5.4 96.84,5.4 99.69,8.25 102.24,8.25 RSPK.A
TXD
  Bottom 0.406: IC7.3 52.07,34.29 46.35,34.29 45.09,33.02 37.47,30.8 37.1,30.8 arc-56 34.71,32.08 34.27,32.73 arc53 30.77,34.73 XUART.TXD
V_IN
  Bottom 0.406: R19.2 225.11,29.84 C13.1
  Bottom 1.27: C18.+ 226.38,21.91 | D21.C D20.C 212.09,19.37 217.17,14.29 222.25,14.29 226.06,18.1 C18.+ | IC3.IN 223.52,38.1 220.66,35.24 220.66,31.75 C13.1 226.06,26.35 C18.+
VCC  (via drill 0.8, 0.8 pad 1.27)  (1 unrouted)
  Top 0.406: R8.E 33.34,16.51 33.34,23.81 R7.1 34.92,27.3 C4.+ | R5.2 D19.C | XUART.VCC 30.16,26.99 30.16,25.08 28.57,23.49 XPWR.2
  Top 1.016: IC7.7 | IC7.7 58.74,21.27 | IC7.20 IC7.21 64.77,18.73 61.91,21.27 | IC1.2 55.33,30.9 55.02,30.71 54.93,30.8 arc32 52.66,27.61 52.08,26 arc-25 51.07,24.4 50.76,24.09 arc45 50.16,22.65 arc31 50.55,21.27 arc36 52.14,19.89 C3.1 55.38,19.49 arc-28 56.71,20.82 57.47,21.27 IC7.7 | XPWR.2 26.04,23.49 24.18,25.35 arc45 21.75,26.35 16.32,26.35 arc-9 14.18,26.53 v13.34,26.67 | C4.+ 34.32,27.41 arc19 37.9,28.43 41.66,30.23 v41.59,30.16 | 61.91,21.27 C2.1 | IC7.7 61.91,21.27
  Bottom 0.406: IC7.21 71.44,20 75.25,21.27 79.69,25.72 86.04,25.72 R5.2
  Bottom 1.016: v41.59,30.16 52.39,30.16 IC1.2 | C4.+ 33.97,27.3 31.43,26.03 28.26,23.49 XPWR.2 | J1.2 3.49,28.65 arc-45 4.12,30.15 arc-45 5.99,30.8 8.08,30.8 arc-45 10,30 v13.34,26.67
  Bottom 1.27: J2.2 232.41,50.8 233.36,49.85 IC3.OUT 233.36,36.51 C11.1 237.49,32.38 237.49,21.59 233.04,17.14 C17.+ 233.04,8.57 228.28,3.81 R16.2 213.68,4.13 209.87,7.94 209.87,11.75 XDCF.VCC
XTAL1
  Top 0.406: IC7.10 57.15,13.65 Q.1 C6.1
XTAL2
  Top 0.406: C7.1 Q.2 IC7.9
(copper drawn outside any net)
  shapes: Top circle x2

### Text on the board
Top: (c) 2006 Georg-Johann Lay
Document: <--- Oben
